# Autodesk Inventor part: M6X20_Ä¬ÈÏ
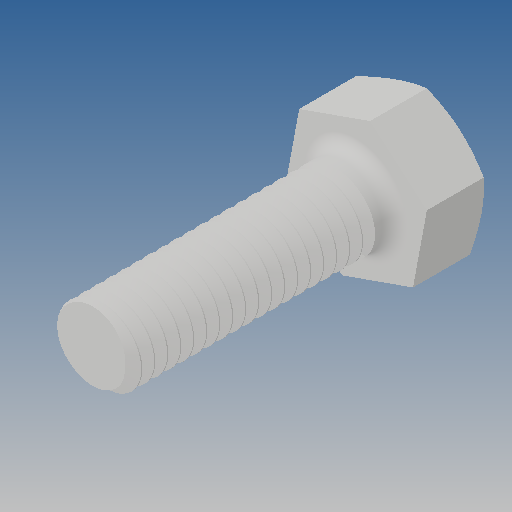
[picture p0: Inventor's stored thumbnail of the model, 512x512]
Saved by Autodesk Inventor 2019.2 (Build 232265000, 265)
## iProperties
Created: 2010-06
Part Number: M6X20_Ä¬ÈÏ
Material: Ogólny
Document SubType Name: Modeling
Designer: CADENGINEERING4
Density: 1 g/cm^3
Appearance: Domyślna
Author: CADENGINEERING4
Revision Number: ÈÎºÎ
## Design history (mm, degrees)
feature "NONE"
node "Bryła1"
